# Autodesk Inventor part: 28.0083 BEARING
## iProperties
Created: 2006-12
Part Number: 28.0083 BEARING
Document SubType Name: Modeling
Designer: Andy Moles
Material: Steel
Density: 7.85 g/cm^3
Author: Andy Moles
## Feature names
1. Extrusion1
2. Extrusion2
3. Mirror1
